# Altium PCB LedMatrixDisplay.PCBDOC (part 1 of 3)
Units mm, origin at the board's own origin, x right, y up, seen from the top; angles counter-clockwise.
Board outline 305.05 x 54.1 mm, 4 copper layers (Top Layer, POWER, GROUND, Bottom Layer); 103 components, 165 nets, 805 pads, 317 vias.
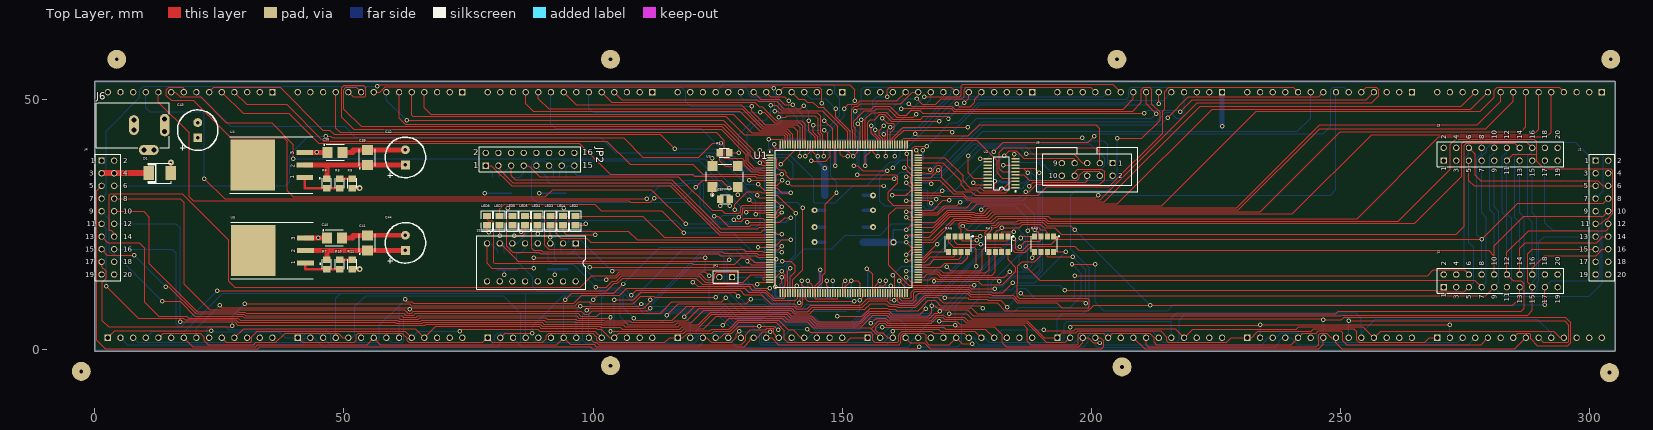
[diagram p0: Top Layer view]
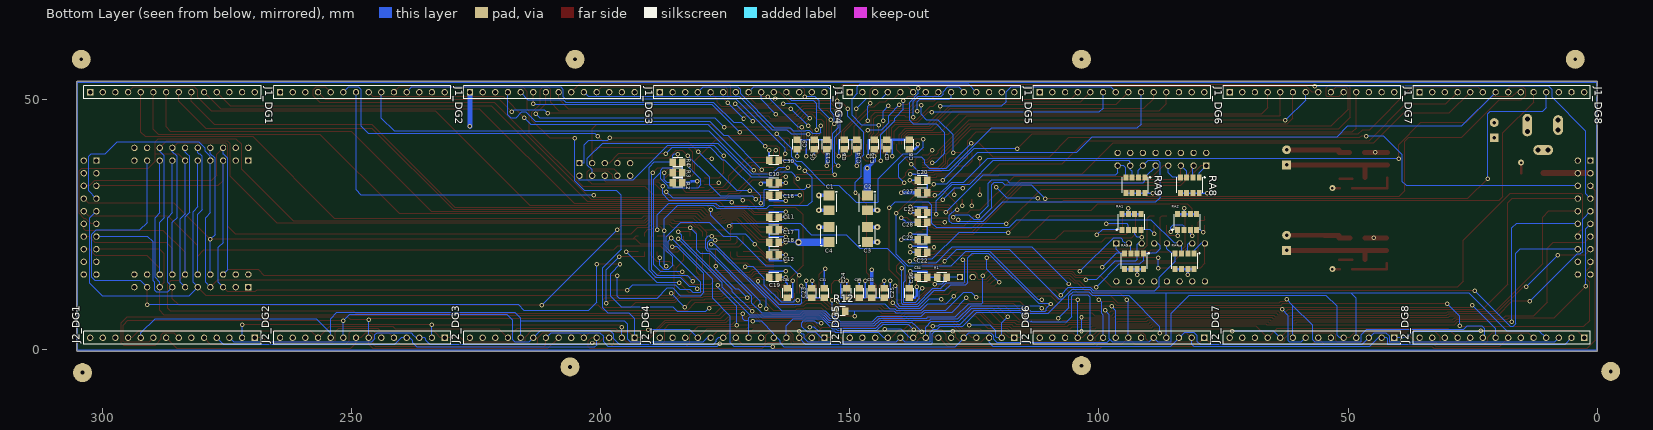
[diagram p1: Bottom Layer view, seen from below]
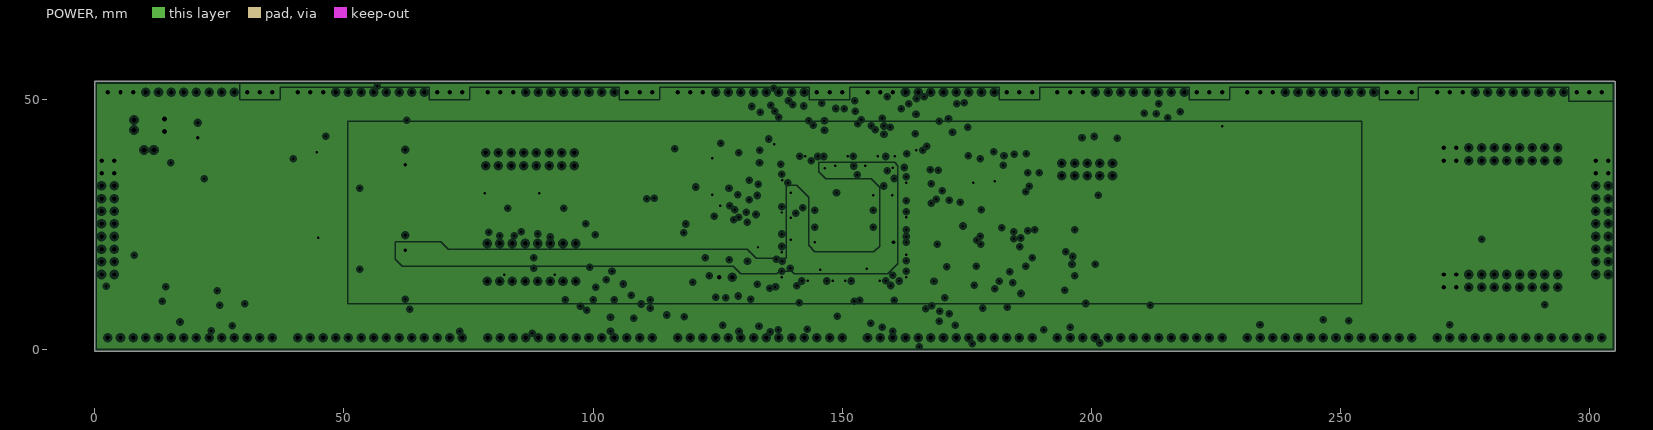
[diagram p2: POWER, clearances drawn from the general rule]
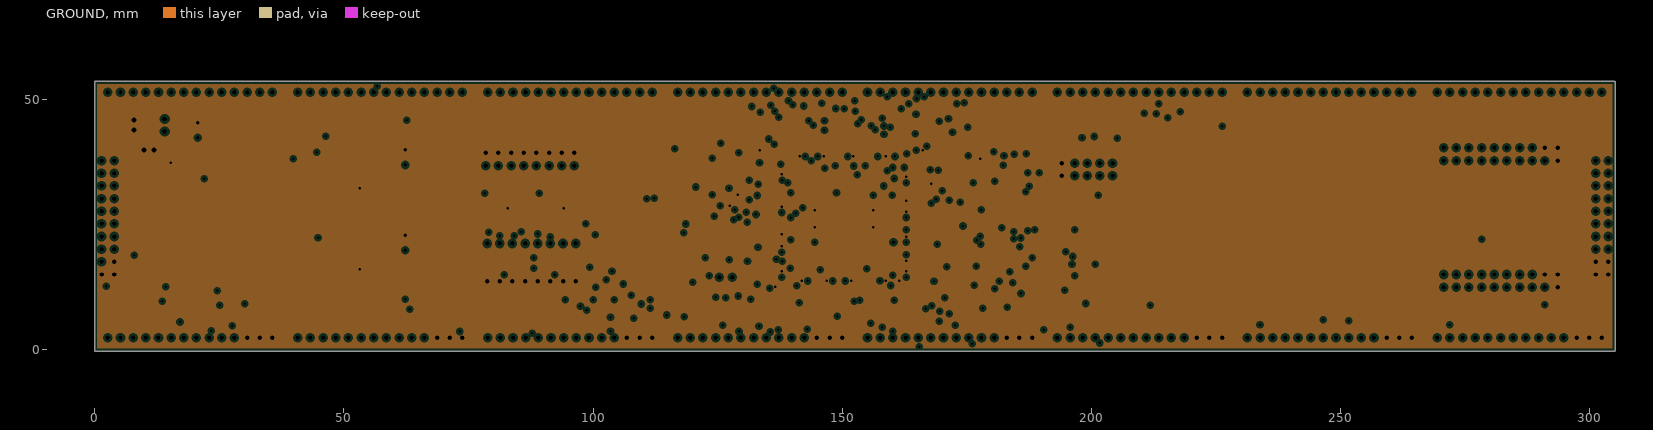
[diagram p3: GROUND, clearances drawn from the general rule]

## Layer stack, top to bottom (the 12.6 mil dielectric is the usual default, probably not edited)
Top Layer: signal copper 0.0356
Dielectric: core 0.32, FR-4, Dk 4.8
POWER: plane copper 0.0356, net (Multiple Nets)
Dielectric: prepreg 0.32, FR-4, Dk 4.8
GROUND: plane copper 0.0356, net GND
Dielectric: core 0.32, FR-4, Dk 4.8
Bottom Layer: signal copper 0.0356

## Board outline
304.927,-0.381 ccw(c304.927,-0.254) 305.055,-0.254 305.055,53.594 ccw(c304.927,53.594) 304.927,53.721 0.127,53.721 ccw(c0.127,53.594) 0,53.594 0,-0.254 ccw(c0.127,-0.254) 0.127,-0.381

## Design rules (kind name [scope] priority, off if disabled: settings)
Clearance [All] p1: gap=0.2
FabricationTestPointUsage TestPointUsage [All] p1: valid=0 allowmultiple=FALSE
FabricationTestpoint Testpoint [All] p1: side=3 testpointundercomponent=TRUE minsize=1.016 maxsize=2.54 preferedsize=1.524 minholesize=0 maxholesize=1.016 preferedholesize=0.813 testpointgrid=0.025 allowsidetop=TRUE allowsidebottom=TRUE usegrid=TRUE gridtolerance=0
HoleSize HoleSize_PowerPads [IsPad And (PadXSize_AllLayers <> PadYSize_AllLayers) And OnMultiLayer] p1: absolutevalues=TRUE maxlimit=2.54 minlimit=0 maxpercent=80.000 minpercent=20.000
HoleSize [All] p2: absolutevalues=TRUE maxlimit=2.54 minlimit=0.025 maxpercent=80.000 minpercent=20.000
PlaneClearance [All] p1: clearance=0.508
PlaneConnect [All] p1: planeconnectstyle=Relief reliefexpansion=0.508 reliefentries=4 reliefconductorwidth=0.254 reliefairgap=0.254
PolygonConnect [All] p1: connectstyle=Relief reliefconductorwidth=0.254 reliefentries=4 polygonreliefangle="90 Angle"
RoomDefinition U_FPGA_U1 [InComponentClass('U_FPGA_U1')] p1: confinementstyle=ConfineIn formatcopy=TRUE lockcomponents=FALSE outline 127.635,6.096 175.895,6.096 175.895,46.736 127.635,46.736
RoomDefinition LED_SW [InComponentClass('LED_SW')] p2: confinementstyle=ConfineIn formatcopy=TRUE lockcomponents=FALSE outline 96.647,13.716 122.047,13.716 122.047,37.846 96.647,37.846
RoomDefinition DG8 [InComponentClass('DG8')] p3: confinementstyle=ConfineIn formatcopy=TRUE lockcomponents=FALSE outline 38.227,-0.254 0.127,-0.254 0.127,53.594 38.227,53.594
RoomDefinition DG7 [InComponentClass('DG7')] p4: confinementstyle=ConfineIn formatcopy=TRUE lockcomponents=FALSE outline 76.327,-0.254 38.227,-0.254 38.227,53.594 76.327,53.594
RoomDefinition DG6 [InComponentClass('DG6')] p5: confinementstyle=ConfineIn formatcopy=TRUE lockcomponents=FALSE outline 114.427,-0.254 76.327,-0.254 76.327,53.594 114.427,53.594
RoomDefinition DG5 [InComponentClass('DG5')] p6: confinementstyle=ConfineIn formatcopy=TRUE lockcomponents=FALSE outline 152.527,-0.254 114.427,-0.254 114.427,53.594 152.527,53.594
RoomDefinition DG3 [InComponentClass('DG3')] p7: confinementstyle=ConfineIn formatcopy=TRUE lockcomponents=FALSE outline 228.727,-0.254 190.627,-0.254 190.627,53.594 228.727,53.594
RoomDefinition DG2 [InComponentClass('DG2')] p8: confinementstyle=ConfineIn formatcopy=TRUE lockcomponents=FALSE outline 266.827,-0.254 228.727,-0.254 228.727,53.594 266.827,53.594
RoomDefinition DG1 [InComponentClass('DG1')] p9: confinementstyle=ConfineIn formatcopy=TRUE lockcomponents=FALSE outline 304.927,-0.254 266.827,-0.254 266.827,53.594 304.927,53.594
RoomDefinition DG4 [InComponentClass('DG4')] p10: confinementstyle=ConfineIn formatcopy=TRUE lockcomponents=FALSE outline 190.627,-0.254 152.527,-0.254 152.527,53.594 190.627,53.594
RoomDefinition PWR [InComponentClass('PWR')] p11: confinementstyle=ConfineIn formatcopy=TRUE lockcomponents=FALSE outline 204.597,13.716 270.637,13.716 270.637,41.656 204.597,41.656
RoutingVias ViasStyle_PowerNets [InNetClass('PowerNets')] p1: holewidth=0.5 width=0.9 viastyle="Through Hole" minholewidth=0.5 minwidth=0.9 maxholewidth=0.5 maxwidth=2.5
RoutingVias [All] p2: holewidth=0.5 width=0.9 viastyle="Through Hole" minholewidth=0.5 minwidth=0.9 maxholewidth=0.5 maxwidth=0.9
SilkscreenOverComponentPads [All] p1: minsilkscreentomaskgap=0.254
SolderMaskExpansion [All] p1: expansion=0.102
Width Width_Power [InNetClass('PowerNets')] p1: maxlimit=2 minlimit=0.2 preferedwidth=0.3 toplayer_prefwidth=0.2 minimp=50.000000 maximp=50.000000 favimp=50.000000
Width [All] p2: maxlimit=2 minlimit=0.2 preferedwidth=0.2
22 further rules are at their usual default settings.

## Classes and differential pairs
net class PowerNets: 6V GND VCCINT VCCO
component class DG1: C45_DG1 C46_DG1 D2_DG1 D3_DG1 GNDTP1_DG1 J1_DG1 J2_DG1 Q1_DG1 Q2_DG1 Q3_DG1 Q4_DG1 Q5_DG1 Q6_DG1 Q7_DG1 Q8_DG1 Q9_DG1 Q10_DG1 Q11_DG1 Q12_DG1 Q13_DG1 Q14_DG1 Q15_DG1 Q16_DG1 R12_DG1 R13_DG1 R14_DG1 R15_DG1 R16_DG1 R17_DG1 R18_DG1 R19_DG1 R20_DG1 R21_DG1 R22_DG1 R23_DG1 R24_DG1 R25_DG1 R26_DG1 TB_DG1 U6_DG1 U7_DG1 U8_DG1 U9_DG1
component class DG2: C45_DG2 C46_DG2 D2_DG2 D3_DG2 GNDTP1_DG2 J1_DG2 J2_DG2 Q1_DG2 Q2_DG2 Q3_DG2 Q4_DG2 Q5_DG2 Q6_DG2 Q7_DG2 Q8_DG2 Q9_DG2 Q10_DG2 Q11_DG2 Q12_DG2 Q13_DG2 Q14_DG2 Q15_DG2 Q16_DG2 R12_DG2 R13_DG2 R14_DG2 R15_DG2 R16_DG2 R17_DG2 R18_DG2 R19_DG2 R20_DG2 R21_DG2 R22_DG2 R23_DG2 R24_DG2 R25_DG2 R26_DG2 TB_DG2 U6_DG2 U7_DG2 U8_DG2 U9_DG2
component class DG3: C45_DG3 C46_DG3 D2_DG3 D3_DG3 GNDTP1_DG3 J1_DG3 J2_DG3 Q1_DG3 Q2_DG3 Q3_DG3 Q4_DG3 Q5_DG3 Q6_DG3 Q7_DG3 Q8_DG3 Q9_DG3 Q10_DG3 Q11_DG3 Q12_DG3 Q13_DG3 Q14_DG3 Q15_DG3 Q16_DG3 R12_DG3 R13_DG3 R14_DG3 R15_DG3 R16_DG3 R17_DG3 R18_DG3 R19_DG3 R20_DG3 R21_DG3 R22_DG3 R23_DG3 R24_DG3 R25_DG3 R26_DG3 TB_DG3 U6_DG3 U7_DG3 U8_DG3 U9_DG3
component class DG4: C45_DG4 C46_DG4 D2_DG4 D3_DG4 GNDTP1_DG4 J1_DG4 J2_DG4 Q1_DG4 Q2_DG4 Q3_DG4 Q4_DG4 Q5_DG4 Q6_DG4 Q7_DG4 Q8_DG4 Q9_DG4 Q10_DG4 Q11_DG4 Q12_DG4 Q13_DG4 Q14_DG4 Q15_DG4 Q16_DG4 R12_DG4 R13_DG4 R14_DG4 R15_DG4 R16_DG4 R17_DG4 R18_DG4 R19_DG4 R20_DG4 R21_DG4 R22_DG4 R23_DG4 R24_DG4 R25_DG4 R26_DG4 TB_DG4 U6_DG4 U7_DG4 U8_DG4 U9_DG4
component class DG5: C45_DG5 C46_DG5 D2_DG5 D3_DG5 GNDTP1_DG5 J1_DG5 J2_DG5 Q1_DG5 Q2_DG5 Q3_DG5 Q4_DG5 Q5_DG5 Q6_DG5 Q7_DG5 Q8_DG5 Q9_DG5 Q10_DG5 Q11_DG5 Q12_DG5 Q13_DG5 Q14_DG5 Q15_DG5 Q16_DG5 R12_DG5 R13_DG5 R14_DG5 R15_DG5 R16_DG5 R17_DG5 R18_DG5 R19_DG5 R20_DG5 R21_DG5 R22_DG5 R23_DG5 R24_DG5 R25_DG5 R26_DG5 TB_DG5 U6_DG5 U7_DG5 U8_DG5 U9_DG5
component class DG6: C45_DG6 C46_DG6 D2_DG6 D3_DG6 GNDTP1_DG6 J1_DG6 J2_DG6 Q1_DG6 Q2_DG6 Q3_DG6 Q4_DG6 Q5_DG6 Q6_DG6 Q7_DG6 Q8_DG6 Q9_DG6 Q10_DG6 Q11_DG6 Q12_DG6 Q13_DG6 Q14_DG6 Q15_DG6 Q16_DG6 R12_DG6 R13_DG6 R14_DG6 R15_DG6 R16_DG6 R17_DG6 R18_DG6 R19_DG6 R20_DG6 R21_DG6 R22_DG6 R23_DG6 R24_DG6 R25_DG6 R26_DG6 TB_DG6 U6_DG6 U7_DG6 U8_DG6 U9_DG6
component class DG7: C45_DG7 C46_DG7 D2_DG7 D3_DG7 GNDTP1_DG7 J1_DG7 J2_DG7 Q1_DG7 Q2_DG7 Q3_DG7 Q4_DG7 Q5_DG7 Q6_DG7 Q7_DG7 Q8_DG7 Q9_DG7 Q10_DG7 Q11_DG7 Q12_DG7 Q13_DG7 Q14_DG7 Q15_DG7 Q16_DG7 R12_DG7 R13_DG7 R14_DG7 R15_DG7 R16_DG7 R17_DG7 R18_DG7 R19_DG7 R20_DG7 R21_DG7 R22_DG7 R23_DG7 R24_DG7 R25_DG7 R26_DG7 TB_DG7 U6_DG7 U7_DG7 U8_DG7 U9_DG7
component class DG8: C45_DG8 C46_DG8 D2_DG8 D3_DG8 GNDTP1_DG8 J1_DG8 J2_DG8 Q1_DG8 Q2_DG8 Q3_DG8 Q4_DG8 Q5_DG8 Q6_DG8 Q7_DG8 Q8_DG8 Q9_DG8 Q10_DG8 Q11_DG8 Q12_DG8 Q13_DG8 Q14_DG8 Q15_DG8 Q16_DG8 R12_DG8 R13_DG8 R14_DG8 R15_DG8 R16_DG8 R17_DG8 R18_DG8 R19_DG8 R20_DG8 R21_DG8 R22_DG8 R23_DG8 R24_DG8 R25_DG8 R26_DG8 TB_DG8 U6_DG8 U7_DG8 U8_DG8 U9_DG8
component class LED_SW: JP2 LED1 LED2 LED3 LED4 LED5 LED6 LED7 LED8 RA1 RA2 RA3 RA4 RA8 RA9 S1
component class LedMatrixDisplay: C37 EN1 J1 J2 J3 J4 J5 R5 R27 RA5 RA6 RA7 U3
component class PWR: C38 C39 C40 C41 C42 C43 C44 D1 J6 R6 R7 R8 R9 R10 R11 U4 U5
component class U_FPGA_U1_Auto: U1
component class U_FPGA_U1: C1 C2 C3 C4 C5 C6 C7 C8 C9 C10 C11 C12 C13 C14 C15 C16 C17 C18 C19 C20 C21 C22 C23 C24 C25 C26 C27 C28 C29 C30 C31 C32 C34 C35 C36 JP1 R1 R2 R3 R4 U2
net class ADDR[2..0]: ADDR0 ADDR1 ADDR2
net class BOARD_ADDR[7..0]: SW0 SW1 SW2 SW3 SW4 SW5 SW6 SW7
net class DATA[7..0]: DATA0 DATA1 DATA2 DATA3 DATA4 DATA5 DATA6 DATA7
net class GREEN[4..0]: GREEN0 GREEN1 GREEN2 GREEN3 GREEN4
net class LED[7..0]: LED0 LED1 LED2 LED3 LED4 LED5 LED6 LED7
net class RED[4..0]: RED0 RED1 RED2 RED3 RED4
net class ROWA[6..0]: ROWA0 ROWA1 ROWA2 ROWA3 ROWA4 ROWA5 ROWA6
net class ROWB[6..0]: ROWB0 ROWB1 ROWB2 ROWB3 ROWB4 ROWB5 ROWB6
net class ROWC[6..0]: ROWC0 ROWC1 ROWC2 ROWC3 ROWC4 ROWC5 ROWC6
net class ROWD[6..0]: ROWD0 ROWD1 ROWD2 ROWD3 ROWD4 ROWD5 ROWD6
net class ROWE[6..0]: ROWE0 ROWE1 ROWE2 ROWE3 ROWE4 ROWE5 ROWE6
net class ROWF[6..0]: ROWF0 ROWF1 ROWF2 ROWF3 ROWF4 ROWF5 ROWF6
net class ROWG[6..0]: ROWG0 ROWG1 ROWG2 ROWG3 ROWG4 ROWG5 ROWG6
net class ROWH[6..0]: ROWH0 ROWH1 ROWH2 ROWH3 ROWH4 ROWH5 ROWH6
net class JUMPERS[7..0]: JUMPERS0 JUMPERS1 JUMPERS2 JUMPERS3 JUMPERS4 JUMPERS5 JUMPERS6 JUMPERS7
channel class DigitHolder: DG1 DG2 DG3 DG4 DG5 DG6 DG7 DG8
net class ENABLE[7..0]: ENABLE0 ENABLE1 ENABLE2 ENABLE3 ENABLE4 ENABLE5 ENABLE6 ENABLE7

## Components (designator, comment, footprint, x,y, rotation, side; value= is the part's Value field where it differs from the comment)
C1 "10uF" MCCT-B 154.177,29.373 r270 bottom locked
C2 "10uF" MCCT-B 146.477,29.373 r270 bottom locked
C3 "10uF" MCCT-B 146.477,22.973 r90 bottom locked
C4 "10uF" MCCT-B 154.177,22.973 r90 bottom locked
C5 "0.1uF" CC2012-0805 157.077,41.073 r270 bottom
C6 "0.1uF" CC2012-0805 151.077,41.073 r270 bottom
C7 "0.1uF" CC2012-0805 142.577,41.073 r270 bottom
C8 "0.1uF" CC2012-0805 138.077,41.073 r270 bottom
C9 "0.1uF" CC2012-0805 160.577,41.073 r270 bottom
C10 "0.1uF" CC2012-0805 165.227,33.423 r180 bottom
C11 "0.1uF" CC2012-0805 165.227,26.423 r180 bottom
C12 "0.1uF" CC2012-0805 165.227,18.923 r180 bottom
C13 "0.1uF" CC2012-0805 154.577,41.073 r270 bottom
C14 "0.1uF" CC2012-0805 148.577,41.073 r270 bottom
C15 "0.1uF" CC2012-0805 145.077,41.073 r270 bottom
C16 "0.1uF" CC2012-0805 165.227,30.923 r180 bottom
C17 "0.1uF" CC2012-0805 165.227,23.923 r180 bottom
C18 "0.1uF" CC2012-0805 165.227,21.423 r180 bottom
C19 "0.1uF" CC2012-0805 165.227,14.423 r0 bottom
C20 "0.1uF" CC2012-0805 135.427,33.923 r180 bottom
C21 "0.1uF" CC2012-0805 135.427,27.423 r180 bottom
C22 "0.1uF" CC2012-0805 135.427,19.423 r180 bottom
C23 "0.1uF" CC2012-0805 157.577,11.273 r270 bottom
C24 "0.1uF" CC2012-0805 150.577,11.273 r270 bottom
C25 "0.1uF" CC2012-0805 143.077,11.273 r270 bottom
C26 "0.1uF" CC2012-0805 138.077,11.273 r270 bottom
C27 "0.1uF" CC2012-0805 135.427,31.423 r180 bottom
C28 "0.1uF" CC2012-0805 135.427,25.423 r180 bottom
C29 "0.1uF" CC2012-0805 135.427,21.923 r180 bottom
C30 "0.1uF" CC2012-0805 165.227,37.923 r0 bottom
C31 "0.1uF" CC2012-0805 155.077,11.273 r270 bottom
C32 "0.1uF" CC2012-0805 145.577,11.273 r270 bottom
C34 "100nF" CC2012-0805 135.427,14.423 r0 bottom
C35 "100nF" CC2012-0805 148.077,11.273 r90 bottom
C36 "100nF" CC2012-0805 162.577,11.273 r90 bottom
C37 "100nF" CC2012-0805 126.492,30.099 r0 top
C38 "10uF" MCCT-B 48.26,39.497 r0 top locked
C39 "10uF" MCCT-B 54.737,38.457 r90 top locked
C40 "10uF" MCCT-B 48.109,22.352 r0 top locked
C41 "10uF" MCCT-B 54.737,21.312 r90 top locked
C42 "470uF 16V" RB8/3.5 62.357,38.481 r180 top
C43 "470uF 16V" RB8/3.5 20.701,43.942 r180 top
C44 "470uF 16V" RB8/3.5 62.357,21.336 r180 top
D1 "SMBJ5341B" DO214 13.081,35.306 r180 top
J1 "Header 20" HDR2X10 301.117,37.846 r270 top
J1_DG1 "Header 14" HDR1X14 302.387,51.562 r180 bottom (schematic designator J1)
J1_DG2 "Header 14" HDR1X14 264.287,51.562 r180 bottom (schematic designator J1)
J1_DG3 "Header 14" HDR1X14 226.187,51.562 r180 bottom (schematic designator J1)
J1_DG4 "Header 14" HDR1X14 188.087,51.562 r180 bottom (schematic designator J1)
J1_DG5 "Header 14" HDR1X14 149.987,51.562 r180 bottom (schematic designator J1)
J1_DG6 "Header 14" HDR1X14 111.887,51.562 r180 bottom (schematic designator J1)
J1_DG7 "Header 14" HDR1X14 73.787,51.562 r180 bottom (schematic designator J1)
J1_DG8 "Header 14" HDR1X14 35.687,51.562 r180 bottom (schematic designator J1)
J2 "Header 20" HDR2X10 270.637,12.446 r0 top
J2_DG1 "Header 14" HDR1X14 269.367,2.286 r0 bottom (schematic designator J2)
J2_DG2 "Header 14" HDR1X14 231.267,2.286 r0 bottom (schematic designator J2)
J2_DG3 "Header 14" HDR1X14 193.167,2.286 r0 bottom (schematic designator J2)
J2_DG4 "Header 14" HDR1X14 155.067,2.286 r0 bottom (schematic designator J2)
J2_DG5 "Header 14" HDR1X14 116.967,2.286 r0 bottom (schematic designator J2)
J2_DG6 "Header 14" HDR1X14 78.867,2.286 r0 bottom (schematic designator J2)
J2_DG7 "Header 14" HDR1X14 40.767,2.286 r0 bottom (schematic designator J2)
J2_DG8 "Header 14" HDR1X14 2.667,2.286 r0 bottom (schematic designator J2)
J3 "Header 20" HDR2X10 270.637,37.846 r0 top
J4 "Header 20" HDR2X10 1.397,37.846 r270 top
J5 "70246-1022" HDR2X5_LP 204.217,37.338 r180 top
J6 "KLD-0202-B" KLD-0202 0.381,44.958 r0 top
JP1 "Header 2" HDR1X2 127.889,14.478 r180 top
JP2 "Header 8X2" HDR2X8 78.487,36.83 r0 top
LED1 "HSMH-C170" "SMD _LED" 93.98,25.781 r90 top
LED2 "HSMH-C170" "SMD _LED" 96.52,25.781 r90 top
LED3 "HSMH-C170" "SMD _LED" 91.44,25.781 r90 top
LED4 "HSMH-C170" "SMD _LED" 88.9,25.781 r90 top
LED5 "HSMH-C170" "SMD _LED" 86.36,25.781 r90 top
LED6 "HSMH-C170" "SMD _LED" 83.82,25.781 r90 top
LED7 "HSMH-C170" "SMD _LED" 81.28,25.781 r90 top
LED8 "HSMH-C170" "SMD _LED" 78.74,25.781 r90 top
R1 "1K" CC2012-0805 131.495,14.423 r180 bottom
R2 "4K7" CC2012-0805 184.531,33.401 r0 bottom
R3 "4K7" CC2012-0805 184.531,35.433 r0 bottom
R4 "4K7" CC2012-0805 184.531,37.465 r0 bottom
R5 "33R" CC2012-0805 126.365,39.37 r0 top
R6 "120R" CC2012-0805 46.609,33.274 r270 top locked
R7 "120R" CC2012-0805 46.609,17.018 r270 top locked
R8 "100R" CC2012-0805 49.149,33.274 r90 top locked
R9 "100R" CC2012-0805 51.689,33.274 r90 top locked
R10 "47R" CC2012-0805 49.149,17.018 r90 top locked
R11 "5R6" CC2012-0805 51.689,17.018 r270 top locked
R12 "47R" CC2012-0805 151.892,7.62 r180 bottom
RA1 "270R" MNR34 93.472,25.527 r90 bottom
RA2 "270R" MNR34 82.296,25.527 r90 bottom
RA3 "4K7" MNR34 92.964,17.653 r270 bottom
RA4 "4K7" MNR34 82.804,17.653 r270 bottom
RA5 "47R" MNR34 190.501,21.082 r270 top
RA6 "47R" MNR34 173.229,21.082 r270 top
RA7 "47R" MNR34 181.357,21.082 r270 top
RA8 "4K7" MNR34 81.788,32.893 r270 bottom
RA9 "4K7" MNR34 92.71,32.893 r270 bottom
S1 "A6ER-8104" DIP-16-KEY 96.52,21.209 r180 top
U1 "XC2S300E-6PQ208C" PQ208 150.327,26.173 r0 top locked
U2 "XCF02SVO20C" VO20 181.991,35.306 r90 top
U3 "QSMO_4200" QSMO_4200 123.952,32.131 r0 top
U4 "LM1084IS-ADJ" TO-263 42.164,34.417 r90 top
U5 "LM1084IS-ADJ" TO-263 42.291,17.272 r90 top

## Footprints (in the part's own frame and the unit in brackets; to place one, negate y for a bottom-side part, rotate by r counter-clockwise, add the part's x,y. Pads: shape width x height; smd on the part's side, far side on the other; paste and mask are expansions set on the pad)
CC2012-0805 [mm]
  rect 1.3x1.5 smd: 1(-0.95,0) 2(0.95,0)
  silkscreen extent -1,-0.9 1,0.9
DIP-16-KEY [mm]
  rect 1.27x1.27 hole 0.9: 1(0,0)
  round 1.27 hole 0.9: 2(2.54,0) 3(5.08,0) 4(7.62,0) 5(10.16,0) 6(12.7,0) 7(15.24,0) 8(17.78,0) 9(17.78,7.62) 10(15.24,7.62) 11(12.7,7.62) 12(10.16,7.62) 13(7.62,7.62) 14(5.08,7.62) 15(2.54,7.62) 16(0,7.62)
  silkscreen extent -2.05,-1.59 19.83,9.2
DO214 [mil]
  rect 85x110 smd: 1(-87.5,0) 2(87.5,0)
  silkscreen extent -90,-78 90,78
HDR1X2 [mm]
  rect 1.27x1.27 hole 0.9: 1(0,0)
  round 1.27 hole 0.9: 2(2.54,0)
  silkscreen extent -1.27,-1.27 3.81,1.27
HDR1X14 [mm]
  rect 1.27x1.27 hole 0.9: 1(0,0)
  round 1.27 hole 0.9: 2(2.54,0) 3(5.08,0) 4(7.62,0) 5(10.16,0) 6(12.7,0) 7(15.24,0) 8(17.78,0) 9(20.32,0) 10(22.86,0) 11(25.4,0) 12(27.94,0) 13(30.48,0) 14(33.02,0)
  silkscreen extent -1.27,-1.27 34.29,1.27
HDR2X5_LP [mm]
  rect 1.27x1.27 hole 0.9: 1(0,0)
  round 1.27 hole 0.9: 2(0,2.54) 3(2.54,0) 4(2.54,2.54) 5(5.08,0) 6(5.08,2.54) 7(7.62,0) 8(7.62,2.54) 9(10.16,0) 10(10.16,2.54)
  silkscreen extent -5.08,-3.18 15.24,5.72
HDR2X8 [mm]
  rect 1.27x1.27 hole 0.9: 1(0,0)
  round 1.27 hole 0.9: 2(0,2.54) 3(2.54,0) 4(2.54,2.54) 5(5.08,0) 6(5.08,2.54) 7(7.62,0) 8(7.62,2.54) 9(10.16,0) 10(10.16,2.54) 11(12.7,0) 12(12.7,2.54) 13(15.24,0) 14(15.24,2.54) 15(17.78,0) 16(17.78,2.54)
  silkscreen extent -1.27,-1.27 19.05,3.81
HDR2X10 [mm]
  rect 1.27x1.27 hole 0.9: 1(0,0)
  round 1.27 hole 0.9: 2(0,2.54) 3(2.54,0) 4(2.54,2.54) 5(5.08,0) 6(5.08,2.54) 7(7.62,0) 8(7.62,2.54) 9(10.16,0) 10(10.16,2.54) 11(12.7,0) 12(12.7,2.54) 13(15.24,0) 14(15.24,2.54) 15(17.78,0) 16(17.78,2.54) 17(20.32,0) 18(20.32,2.54) 19(22.86,0) 20(22.86,2.54)
  silkscreen extent -1.27,-1.27 24.13,3.81
KLD-0202 [mm] "PCB Mount DC Power Jack with 2.1mm or 2.5mm center pin"
  oval 2x4.5 all layers, no hole: 1(13.7,0)
  round 1.5 hole 1: 1A(13.7,-1.25) 1B(13.7,1.25) 2A(9.5,-5) 2B(11.5,-5) 3A(7.5,-1) 3B(7.5,1)
  oval 4x2 all layers, no hole: 2(10.5,-5)
  oval 2x4 all layers, no hole: 3(7.5,0)
  silkscreen extent 0,-4.5 14.6,4.5
MCCT-B [mm]
  rect 2x2.2 smd: 1(-1.5,0) 2(1.5,0)
  silkscreen extent -2.3,-1.6 1.8,1.6
MNR34 [mm]
  rect 1.2x1 smd: 1(-1.575,1.905) 2(-1.575,0.635) 3(-1.575,-0.635) 4(-1.575,-1.905) 5(1.575,-1.905) 6(1.575,-0.635) 7(1.575,0.635) 8(1.575,1.905)
  silkscreen extent -1.67,-2.62 1.55,3.07
PQ208 [mm] "208-Pin Plastic Quad Flat Pack (PQ208)"
  rect 1.55x0.3 smd: 1(-14.9,12.75) 2(-14.9,12.25) 3(-14.9,11.75) 4(-14.9,11.25) 5(-14.9,10.75) 6(-14.9,10.25) 7(-14.9,9.75) 8(-14.9,9.25) 9(-14.9,8.75) 10(-14.9,8.25) 11(-14.9,7.75) 12(-14.9,7.25) 13(-14.9,6.75) 14(-14.9,6.25) 15(-14.9,5.75) 16(-14.9,5.25) 17(-14.9,4.75) 18(-14.9,4.25) 19(-14.9,3.75) 20(-14.9,3.25) 21(-14.9,2.75) 22(-14.9,2.25) 23(-14.9,1.75) 24(-14.9,1.25) 25(-14.9,0.75) 26(-14.9,0.25) 27(-14.9,-0.25) 28(-14.9,-0.75) 29(-14.9,-1.25) 30(-14.9,-1.75) 31(-14.9,-2.25) 32(-14.9,-2.75) 33(-14.9,-3.25) 34(-14.9,-3.75) 35(-14.9,-4.25) 36(-14.9,-4.75) 37(-14.9,-5.25) 38(-14.9,-5.75) 39(-14.9,-6.25) 40(-14.9,-6.75) 41(-14.9,-7.25) 42(-14.9,-7.75) 43(-14.9,-8.25) 44(-14.9,-8.75) 45(-14.9,-9.25) 46(-14.9,-9.75) 47(-14.9,-10.25) 48(-14.9,-10.75) 49(-14.9,-11.25) 50(-14.9,-11.75) 51(-14.9,-12.25) 52(-14.9,-12.75) 105(14.9,-12.75) 106(14.9,-12.25) 107(14.9,-11.75) 108(14.9,-11.25) 109(14.9,-10.75) 110(14.9,-10.25) 111(14.9,-9.75) 112(14.9,-9.25) 113(14.9,-8.75) 114(14.9,-8.25) 115(14.9,-7.75) 116(14.9,-7.25) 117(14.9,-6.75) 118(14.9,-6.25) 119(14.9,-5.75) 120(14.9,-5.25) 121(14.9,-4.75) 122(14.9,-4.25) 123(14.9,-3.75) 124(14.9,-3.25) 125(14.9,-2.75) 126(14.9,-2.25) 127(14.9,-1.75) 128(14.9,-1.25) 129(14.9,-0.75) 130(14.9,-0.25) 131(14.9,0.25) 132(14.9,0.75) 133(14.9,1.25) 134(14.9,1.75) 135(14.9,2.25) 136(14.9,2.75) 137(14.9,3.25) 138(14.9,3.75) 139(14.9,4.25) 140(14.9,4.75) 141(14.9,5.25) 142(14.9,5.75) 143(14.9,6.25) 144(14.9,6.75) 145(14.9,7.25) 146(14.9,7.75) 147(14.9,8.25) 148(14.9,8.75) 149(14.9,9.25) 150(14.9,9.75) 151(14.9,10.25) 152(14.9,10.75) 153(14.9,11.25) 154(14.9,11.75) 155(14.9,12.25) 156(14.9,12.75)
  rect 0.3x1.55 smd: 53(-12.75,-14.9) 54(-12.25,-14.9) 55(-11.75,-14.9) 56(-11.25,-14.9) 57(-10.75,-14.9) 58(-10.25,-14.9) 59(-9.75,-14.9) 60(-9.25,-14.9) 61(-8.75,-14.9) 62(-8.25,-14.9) 63(-7.75,-14.9) 64(-7.25,-14.9) 65(-6.75,-14.9) 66(-6.25,-14.9) 67(-5.75,-14.9) 68(-5.25,-14.9) 69(-4.75,-14.9) 70(-4.25,-14.9) 71(-3.75,-14.9) 72(-3.25,-14.9) 73(-2.75,-14.9) 74(-2.25,-14.9) 75(-1.75,-14.9) 76(-1.25,-14.9) 77(-0.75,-14.9) 78(-0.25,-14.9) 79(0.25,-14.9) 80(0.75,-14.9) 81(1.25,-14.9) 82(1.75,-14.9) 83(2.25,-14.9) 84(2.75,-14.9) 85(3.25,-14.9) 86(3.75,-14.9) 87(4.25,-14.9) 88(4.75,-14.9) 89(5.25,-14.9) 90(5.75,-14.9) 91(6.25,-14.9) 92(6.75,-14.9) 93(7.25,-14.9) 94(7.75,-14.9) 95(8.25,-14.9) 96(8.75,-14.9) 97(9.25,-14.9) 98(9.75,-14.9) 99(10.25,-14.9) 100(10.75,-14.9) 101(11.25,-14.9) 102(11.75,-14.9) 103(12.25,-14.9) 104(12.75,-14.9) 157(12.75,14.9) 158(12.25,14.9) 159(11.75,14.9) 160(11.25,14.9) 161(10.75,14.9) 162(10.25,14.9) 163(9.75,14.9) 164(9.25,14.9) 165(8.75,14.9) 166(8.25,14.9) 167(7.75,14.9) 168(7.25,14.9) 169(6.75,14.9) 170(6.25,14.9) 171(5.75,14.9) 172(5.25,14.9) 173(4.75,14.9) 174(4.25,14.9) 175(3.75,14.9) 176(3.25,14.9) 177(2.75,14.9) 178(2.25,14.9) 179(1.75,14.9) 180(1.25,14.9) 181(0.75,14.9) 182(0.25,14.9) 183(-0.25,14.9) 184(-0.75,14.9) 185(-1.25,14.9) 186(-1.75,14.9) 187(-2.25,14.9) 188(-2.75,14.9) 189(-3.25,14.9) 190(-3.75,14.9) 191(-4.25,14.9) 192(-4.75,14.9) 193(-5.25,14.9) 194(-5.75,14.9) 195(-6.25,14.9) 196(-6.75,14.9) 197(-7.25,14.9) 198(-7.75,14.9) 199(-8.25,14.9) 200(-8.75,14.9) 201(-9.25,14.9) 202(-9.75,14.9) 203(-10.25,14.9) 204(-10.75,14.9) 205(-11.25,14.9) 206(-11.75,14.9) 207(-12.25,14.9) 208(-12.75,14.9)
  silkscreen extent -15.02,-13.73 13.72,13.73
QSMO_4200 [mm]
  rect 2x2 smd: 1(0,0.4) 2(5.08,0.4) 3(5.08,4.6) 4(0,4.6)
  silkscreen extent -1.19,-1.31 6.22,4.95
RB8/3.5 [mil]
  rect 70x70 hole 27.56: 1(0,60)
  round 70 hole 27.56: 2(0,-60)
  silkscreen extent -160,-160 160,160
"SMD _LED" [mm]
  rect 1.3x1.6 smd: 1(0.94,0) 2(-0.96,0)
  silkscreen extent -2.14,-1.15 1.99,1.15
TO-263 [mm]
  rect 1x3.4 smd: 1(0,0) 2(2.54,0) 3(5.08,0)
  rect 10.25x8.9 smd: 4(2.54,10.45)
  silkscreen extent -3.1,-3.13 8.2,15
VO20 [mm]
  rect 0.3x1.65 smd: 1(-2.929,-2.766) 2(-2.279,-2.766) 3(-1.629,-2.766) 4(-0.979,-2.766) 5(-0.329,-2.766) 6(0.321,-2.766) 7(0.971,-2.766) 8(1.621,-2.766) 9(2.271,-2.766) 10(2.921,-2.766) 11(2.921,2.784) 12(2.271,2.784) 13(1.621,2.784) 14(0.971,2.784) 15(0.321,2.784) 16(-0.329,2.784) 17(-0.979,2.784) 18(-1.629,2.784) 19(-2.279,2.784) 20(-2.929,2.784)
  silkscreen extent -3.75,-2.89 3.3,1.56

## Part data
C1 C2 C3 C4 C38 C39 C40 C41 C42 C43 C44: library part CAP_POLAR, "Polar Capacitor"
C5 C6 C7 C8 C9 C10 C11 C12 C13 C14 C15 C16 C17 C18 C19 C20 C21 C22 C23 C24 C25 C26 C27 C28 C29 C30 C31 C32 C34 C35 C36 C37: library part CAP, "Capacitor"
D1: library part BZG03C13, "Zener Diode, 6.2V, 5W"
J1 J2 J3 J4: "Header, 20-Pin"
J1_DG1 J1_DG2 J1_DG3 J1_DG4 J1_DG5 J1_DG6 J1_DG7 J1_DG8 J2_DG1 J2_DG2 J2_DG3 J2_DG4 J2_DG5 J2_DG6 J2_DG7 J2_DG8: "Header, 14-Pin"
J5: library part "Header 5X2", "Header, 5-Pin, Dual row"
J6: "Low Voltage Power Supply Connector"
JP1: "Header, 2-Pin"
JP2: "Header, 8-Pin, Dual row"
LED1 LED2 LED3 LED4 LED5 LED6 LED7 LED8: library part HSMX-C670, "Typical RED GaAs SMD LED Agilent make"
R1 R2 R3 R4 R5 R6 R7 R8 R9 R10 R11 R12: library part RES, "Resistor"
RA1 RA2 RA3 RA4 RA5 RA6 RA7 RA8 RA9: library part MNR34, "3216x4 Resistor Array"
S1: "DIP Switch Side actuator long liver Piano Key"
U1: "Spartan-IIE 1.8V FPGA, 208-Pin PQFP, Standard Performance, Commercial Grade"
U2: "XCF00S Series, Platform Flash In-System Programmable Configuration 3.3V PROM, 20-Pin TSOP, 2-Megabit, Commercial Grade"
U3: "Surface Mount Crystal Oscillator"
U4 U5: "5A Low Dropout Possitive Regulators"

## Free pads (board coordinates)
  round 3.81 hole 0.762: 1(4.445,58.166) 2(304.165,58.166) 3(303.911,-4.699) 4(-2.667,-4.445) 5(103.505,58.166) 6(205.105,58.166) 7(103.505,-3.302) 8(206.121,-3.556)

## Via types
v1: diameter 0.9, hole 0.5, Top Layer to Bottom Layer, 307 vias
v2: diameter 1.2, hole 0.5, Top Layer to Bottom Layer, 9 vias
v3: diameter 1.27, hole 0.711, Top Layer to Bottom Layer, 1 vias

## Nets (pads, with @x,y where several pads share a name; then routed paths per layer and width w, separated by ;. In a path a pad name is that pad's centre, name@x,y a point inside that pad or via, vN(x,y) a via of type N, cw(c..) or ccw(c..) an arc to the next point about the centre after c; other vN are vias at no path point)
6V: C38.1 C40.1 C43.1 D1.2 J1.1 J1.2 J1.3 J1.4 J1_DG1.12 J1_DG1.13 J1_DG1.14 J1_DG2.12 J1_DG2.13 J1_DG2.14 J1_DG3.12 J1_DG3.13 J1_DG3.14 J1_DG4.12 J1_DG4.13 J1_DG4.14 J1_DG5.12 J1_DG5.13 J1_DG5.14 J1_DG6.12 J1_DG6.13 J1_DG6.14 J1_DG7.12 J1_DG7.13 J1_DG7.14 J1_DG8.12 J1_DG8.13 J1_DG8.14 J2.1 J2.2 J2.3 J2.4 J3.1 J3.2 J3.3 J3.4 J4.1 J4.2 J4.3 J4.4 J6.1 J6.1A J6.1B U4.3 U5.3 | length 18.4
  Top Layer w1: U4.3@42.164,39.497 v1(44.577,39.497) C38.1@46.76,39.497 ; U5.3@42.291,22.352 v1(44.831,22.352) C40.1@46.609,22.352
  Top Layer w1.2: J4.3@1.397,35.306 J4.4@3.937,35.306 D1.2@10.859,35.306
ADDR0: RA7.5 U1.110 | length 18.3
  Top Layer w0.2: U1.110@165.227,15.923 169.599,15.923 170.231,15.291 178.791,15.291 179.452,15.952 RA7.5@179.452,19.507
ADDR1: RA7.6 U1.109 | length 20
  Top Layer w0.2: U1.109@165.227,15.423 166.193,15.423 166.263,15.494 169.215,15.494 169.825,14.884 180.061,14.884 180.722,15.545 RA7.6@180.722,19.507
ADDR2: RA7.7 U1.97 | length 33.3
  Top Layer w0.2: U1.97@159.577,11.273 159.577,9.779 v1(160.401,9.779) ; v1(170.942,16.51) 171.755,15.697 177.673,15.697 178.08,16.104 178.08,19.812 178.689,20.422 181.738,20.422 181.992,20.168 RA7.7@181.992,19.507
  Bottom Layer w0.2: v1(160.401,9.779) 161.163,9.779 161.163,9.373 163.653,9.373 167.132,12.852 167.132,14.275 169.368,16.51 v1(170.942,16.51)
CCLK: U1.155 U2.3 | length 23.6
  Top Layer w0.2: U1.155@165.227,38.423 170.568,38.423 174.244,34.747 174.244,33.782 175.591,32.436 177.724,32.436 178.334,31.826 181.915,31.826 183.766,33.677 U2.3@184.758,33.677
CLK_MHZ40: R5.2 U1.185 | length 34.3
  Top Layer w0.2: R5.2@127.315,39.37 v1(129.21,39.37) ; v1(135.662,48.946) 136.779,48.946 137.897,47.828 145.974,47.828 149.077,44.725 U1.185@149.077,41.073
  Bottom Layer w0.2: v1(129.21,39.37) 129.21,42.977 132.207,45.974 134.519,45.974 135.662,47.117 v1(135.662,48.946)
CNT5: J1.5 J2.5 J3.5 J4.5 RA5.4 | length 403.1
  Top Layer w0.2: J4.5@1.397,32.766 0.458,31.826 0.458,1.778 2.109,0.127 32.766,0.127 33.173,0.533 99.467,0.533 99.873,0.127 164.999,0.127 v1(165.405,0.533) ; v1(185.801,22.25) 186.208,22.657 ; v1(185.801,22.377) 186.081,22.657 RA5.4@188.596,22.657 ; v1(194.615,11.811) 268.986,11.811 269.317,11.481 274.752,11.481 J2.5@275.717,12.446 ; J3.5@275.717,37.846 275.717,33.782 276.733,32.766 J1.5@301.117,32.766
  Bottom Layer w0.2: v1(165.405,0.533) 173.203,0.533 173.94,1.27 173.94,6.655 177.47,10.185 177.47,14.046 v1(185.801,22.377) ; v1(185.801,22.25) 186.36,21.692 186.36,19.964 179.858,13.462 179.858,11.582 180.112,11.328 181.407,11.328 182.017,11.938 183.965,11.938 184.854,12.827 193.599,12.827 v1(194.615,11.811) ; J2.5@275.717,12.446 276.657,13.386 276.657,20.447 275.717,21.387 J3.5@275.717,37.846
CNT6: J1.6 J2.6 J3.6 J4.6 RA5.3 | length 395.8
  Top Layer w0.2: v1(46.381,42.748) 47.422,42.748 47.752,42.418 106.122,42.418 110.008,38.532 121.235,38.532 124.054,41.351 v1(125.603,41.351) ; v1(139.065,33.401) 139.725,32.741 v1(158.319,32.741) ; v1(185.598,20.574) 186.716,21.692 189.662,21.692 189.866,21.895 RA5.3@189.866,22.657 189.408,22.657 189.408,23.571 188.951,23.571 v1(188.595,23.927) ; v1(196.596,14.732) 196.647,14.783 267.437,14.783 268.58,15.926 274.778,15.926 J2.6@275.717,14.986 ; J3.6@275.717,40.386 276.987,39.116 276.987,34.874 278.054,33.807 301.549,33.807 302.591,32.766 J1.6@303.657,32.766
  Bottom Layer w0.2: J4.6@3.937,32.766 38.278,32.766 39.142,33.63 39.142,38.989 42.901,42.748 v1(46.381,42.748) ; v1(125.603,41.351) 130.734,36.22 133.985,36.22 134.576,36.811 134.972,37.208 134.972,37.944 135.509,38.481 138.811,38.481 140.208,37.084 140.208,34.544 v1(139.065,33.401) ; v1(158.319,32.741) 159.081,31.979 167.132,31.979 167.132,28.905 167.488,28.55 176.099,28.55 176.734,29.185 186.411,29.185 188.595,27 v1(188.595,23.927) ; v1(185.598,20.574) 184.564,20.574 179.248,15.258 179.248,11.43 180.01,10.668 183.896,10.668 185.42,12.192 186.69,12.192 188.722,10.16 196.088,10.16 196.596,10.668 v1(196.596,14.732) ; J2.6@275.717,14.986 274.778,15.926 274.778,38.278 275.616,39.116 275.717,39.116 J3.6@275.717,40.386
CNT7: J1.7 J2.7 J3.7 J4.7 RA5.2 | length 402.8
  Top Layer w0.2: v1(56.693,52.781) 56.998,53.086 151.461,53.086 152.477,52.07 v1(152.477,49.86) ; v1(152.324,36.754) 153.137,36.754 154.077,35.814 v1(159.004,35.814) ; v1(186.767,16.662) 189.637,13.792 276.911,13.792 J2.7@278.257,12.446 ; v1(187.173,23.724) 188.126,24.677 189.11,24.677 189.834,23.952 190.577,23.952 191.136,23.393 RA5.2@191.136,22.657
  Bottom Layer w0.2: J4.7@1.397,30.226 2.337,31.166 2.337,43.764 9.094,50.521 9.094,52.07 9.805,52.781 v1(56.693,52.781) ; v1(152.324,36.754) 152.959,37.389 152.959,42.52 151.867,43.612 151.867,49.251 v1(152.477,49.86) ; v1(159.004,35.814) 157.557,34.367 157.557,29.718 158.522,28.753 166.116,28.753 166.726,28.143 176.607,28.143 177.242,28.778 184.608,28.778 187.173,26.213 187.173,17.069 v1(186.767,16.662) ; J2.7@278.257,12.446 279.197,13.386 279.197,26.416 278.257,27.356 J3.7@278.257,37.846 278.257,38.659 279.299,39.7 279.299,40.361 280.493,41.554 297.028,41.554 299.466,39.116 302.26,39.116 302.641,38.735 302.641,31.75 J1.7@301.117,30.226
CNT8: J1.8 J2.8 J3.8 J4.8 RA5.1 | length 363.2
  Top Layer w0.2: J4.8@3.937,30.226 17.145,30.226 17.958,29.413 17.958,13.056 23.114,7.899 62.18,7.899 62.853,7.226 63.614,7.226 63.958,7.569 97.675,7.569 98.222,7.022 99.149,7.022 99.848,7.722 110.973,7.722 v1(111.506,8.255) ; v1(184.43,22.149) 184.811,21.768 184.811,20.168 185.166,19.812 186.208,19.812 187.427,21.031 191.948,21.031 192.939,22.022 v1(278.257,22.022) 285.496,29.261 302.692,29.261 J1.8@303.657,30.226 ; RA5.1@192.406,22.657 192.939,22.657 193.574,22.022
  Bottom Layer w0.2: v1(111.506,8.255) 111.913,8.661 125.73,8.661 128.422,5.969 133.858,5.969 134.074,5.753 144.018,5.753 145.199,4.572 152.158,4.572 153.339,5.753 154.075,5.753 155.129,6.807 169.952,6.807 175.565,12.421 175.565,13.284 v1(184.43,22.149) ; J2.8@278.257,14.986 v1(278.257,22.022) 277.318,22.962 277.318,38.303 278.257,39.243 J3.8@278.257,40.386
CNT9: J1.9 J2.9 J3.9 J4.9 RA6.4 | length 384
  Top Layer w0.2: v1(13.615,9.601) 17.171,9.601 20.114,6.658 29.617,6.658 30.001,6.274 61.042,6.274 61.296,6.02 64.948,6.02 65.202,6.274 90.551,6.274 90.856,5.969 96.628,5.969 96.774,5.822 102.179,5.822 102.312,5.69 107.392,5.69 107.722,5.359 116.129,5.359 116.459,5.69 118.771,5.69 121.285,8.204 139.827,8.204 140.513,7.518 143.079,7.518 143.942,8.382 154.051,8.382 155.375,9.706 158.95,9.706 159.639,9.017 161.182,9.017 161.367,8.832 164.534,8.832 166.554,10.852 169.996,10.852 v1(170.561,10.287) 175.133,10.287 175.387,10.033 179.07,10.033 179.324,9.779 181.814,9.779 v1(183.134,8.458) ; RA6.4@171.324,22.657 171.324,21.488 172.391,20.422 176.454,20.422 176.911,19.964 v1(176.911,16.612) ; v1(185.852,11.176) 186.259,10.77 279.121,10.77 J2.9@280.797,12.446
  Bottom Layer w0.2: J4.9@1.397,27.686 2.998,26.086 2.998,19.558 3.506,19.05 4.166,19.05 v1(13.615,9.601) ; v1(170.561,10.287) 172.258,11.984 172.843,11.984 176.911,16.053 v1(176.911,16.612) ; v1(183.134,8.458) v1(185.852,11.176) ; J3.9@280.797,37.846 280.797,28.55 281.737,27.61 281.737,13.386 J2.9@280.797,12.446 282.626,10.617 299.873,10.617 302.464,13.208 302.464,26.34 J1.9@301.117,27.686
CNT10: J1.10 J2.10 J3.10 J4.10 RA6.3 | length 368.2
  Top Layer w0.2: J4.10@3.937,27.686 9.83,27.686 10.999,26.518 10.999,17.094 20.6,7.493 28.896,7.493 28.931,7.458 30.134,7.458 30.404,7.188 62.078,7.188 62.441,6.826 64.027,6.826 64.364,7.163 97.047,7.163 97.587,6.622 100.729,6.622 101.346,7.239 113.538,7.239 115.824,9.525 125.857,9.525 v1(126.619,10.287) ; RA6.3@172.594,22.657 172.594,21.59 173.102,21.082 183.744,21.082 184.074,20.752 184.074,19.914 184.582,19.406 186.665,19.406 187.884,20.625 196.647,20.625 197.46,19.812 279.68,19.812 280.797,18.694 ; J2.10@280.797,14.986 280.797,20.777 286.665,26.645 302.616,26.645 J1.10@303.657,27.686
  Bottom Layer w0.2: v1(126.619,10.287) 129.565,7.341 134.939,7.341 135.726,6.553 144.45,6.553 145.631,5.372 151.826,5.372 153.007,6.553 153.744,6.553 154.811,7.62 163.576,7.62 177.038,21.082 v1(177.75,21.082) ; J2.10@280.797,14.986 280.797,27.026 279.858,27.965 279.858,38.659 280.315,39.116 280.493,39.116 280.797,39.421 J3.10@280.797,40.386
CNT11: J1.11 J2.11 J3.11 J4.11 RA6.2 | length 404.2
  Top Layer w0.2: v1(2.337,12.649) 8.738,6.248 17.78,6.248 18.17,5.858 28.33,5.858 28.804,5.385 60.344,5.385 60.522,5.207 65.812,5.207 65.99,5.385 89.815,5.385 90.145,5.055 95.955,5.055 95.987,5.022 101.709,5.022 101.854,4.877 106.096,4.877 106.426,4.547 117.094,4.547 117.425,4.877 121.133,4.877 123.648,7.391 139.091,7.391 139.777,6.706 143.789,6.706 144.996,5.499 153.459,5.499 155.536,7.576 159.429,7.576 160.09,6.915 165.538,6.915 v1(166.751,8.128) ; v1(176.937,21.844) 176.835,21.742 174.118,21.742 173.864,21.996 RA6.2@173.864,22.657 173.864,23.952 173.457,24.359 173.457,25.248 173.679,25.469 174.752,25.469 174.974,25.248 180.322,25.248 181.389,26.314 190.698,26.314 191.333,25.679 261.57,25.679 271.984,36.093 271.984,41.097 273.05,42.164 288.824,42.164 289.357,41.631 289.357,37.719 290.83,36.246 304.165,36.246 304.597,35.814 304.597,27.28 303.53,26.213 303.251,26.213 302.184,25.146 J1.11@301.117,25.146 ; J3.11@283.337,37.846 284.607,39.116 289.357,39.116
  Bottom Layer w0.2: J4.11@1.397,25.146 2.337,24.206 v1(2.337,12.649) ; v1(166.751,8.128) 166.751,10.21 176.632,20.091 178.246,20.091 178.512,20.357 178.512,21.412 178.08,21.844 v1(176.937,21.844) ; J2.11@283.337,12.446 284.277,13.386 284.277,26.187 283.337,27.127 J3.11@283.337,37.846
CNT12: J1.12 J2.12 J3.12 J4.12 RA6.1 | length 394.2
  Top Layer w0.2: v1(17.145,5.461) 17.148,5.458 28.118,5.458 28.776,4.801 66.218,4.801 66.396,4.978 89.434,4.978 89.79,4.622 101.347,4.622 101.575,4.394 105.461,4.394 105.817,4.039 117.425,4.039 117.856,4.47 121.292,4.47 123.807,6.985 138.862,6.985 139.548,6.299 143.561,6.299 144.761,5.099 153.625,5.099 155.702,7.176 159.194,7.176 159.855,6.515 167.17,6.515 167.945,7.29 v1(167.945,8.738) 168.554,8.738 168.961,8.331 175.87,8.331 177.115,7.087 248.997,7.087 249.479,7.569 286.208,7.569 286.817,8.179 286.817,13.081 286.182,13.716 284.607,13.716 J2.12@283.337,14.986 283.337,19.406 287.732,23.8 303.251,23.8 303.657,24.206 J1.12@303.657,25.146 ; RA6.1@175.134,22.657 v1(177.724,22.657)
  Bottom Layer w0.2: J4.12@3.937,25.146 16.333,25.146 17.145,24.333 v1(17.145,5.461) ; v1(167.945,8.738) 167.945,9.627 178.004,19.685 178.486,19.685 178.918,20.117 178.918,22.174 178.435,22.657 v1(177.724,22.657) ; J2.12@283.337,14.986 283.337,26.543 282.398,27.483 282.398,38.659 282.855,39.116 282.931,39.116 283.337,39.522 J3.12@283.337,40.386
CNT13: J1.13 J2.13 J3.13 J4.13 RA7.4 | length 399.1
  Top Layer w0.2: J4.13@1.397,22.606 2.667,21.336 9.017,21.336 10.11,20.244 10.11,9.398 12.853,6.655 18.492,6.655 18.888,6.258 28.743,6.258 29.21,5.791 60.719,5.791 60.896,5.613 65.431,5.613 65.609,5.791 90.196,5.791 90.526,5.461 96.329,5.461 96.368,5.422 101.893,5.422 102.032,5.283 106.655,5.283 106.985,4.953 116.536,4.953 116.866,5.283 119.685,5.283 122.2,7.798 139.664,7.798 140.35,7.112 143.479,7.112 144.343,7.976 154.534,7.976 155.702,9.144 158.75,9.144 159.311,8.583 160.835,8.583 161.036,8.382 164.719,8.382 166.751,10.414 169.164,10.414 170.307,9.271 181.051,9.271 182.626,7.696 199.34,7.696 200.432,8.788 284.557,8.788 285.877,10.109 J2.13@285.877,12.446 ; RA7.4@179.452,22.657 179.452,23.419 180.468,24.435 181.026,24.435 181.737,25.146 185.598,25.146 185.929,25.477 190.17,25.477 190.882,24.765 195.834,24.765 v1(196.622,23.978)
  Bottom Layer w0.2: v1(196.622,23.978) v1(211.811,8.788) ; J3.13@285.877,37.846 285.877,27.356 286.817,26.416 286.817,13.386 J2.13@285.877,12.446 286.919,11.405 289.052,11.405 289.052,11.43 289.433,11.811 289.433,13.385 289.764,13.716 289.764,21.59 290.78,22.606 J1.13@301.117,22.606
CNT14: J1.14 J2.14 J3.14 J4.14 RA7.3 | length 395.3
  Top Layer w0.2: J4.14@3.937,22.606 3.937,23.266 3.328,23.876 2.998,23.876 2.998,30.937 3.277,31.217 17.552,31.217 26.899,21.869 26.899,13.64 28.093,12.446 97.486,12.446 99.772,14.732 104.521,14.732 105.283,15.494 122.555,15.494 v1(123.317,14.732) ; RA7.3@180.722,22.657 180.722,23.496 181.102,23.876 181.534,23.876 v1(182.017,24.359) 185.534,24.359 186.252,25.077 189.764,25.077 190.482,24.359 192.583,24.359 193.904,23.038 273.152,23.038 274.778,24.663 274.778,40.894 275.209,41.326 284.938,41.326 J3.14@285.877,40.386 ; J2.14@285.877,14.986 285.877,20.244 286.995,21.361 301.346,21.361 302.387,22.403 302.387,22.606 J1.14@303.657,22.606
  Bottom Layer w0.2: v1(123.317,14.732) 123.317,9.398 123.654,9.061 126.194,9.061 128.886,6.369 134.404,6.369 134.62,6.153 144.215,6.153 145.396,4.972 151.992,4.972 153.173,6.153 153.91,6.153 154.97,7.214 167.59,7.214 169.622,9.246 169.622,10.668 178.08,19.126 179.883,19.126 180.721,19.964 180.721,23.063 v1(182.017,24.359) ; J2.14@285.877,14.986 285.877,25.476 284.938,26.416 284.938,38.684 285.877,39.624 J3.14@285.877,40.386
CNT15: J1.15 J2.15 J3.15 J4.15 RA7.2 | length 378.1
  Top Layer w0.2: J4.15@1.397,20.066 2.591,18.872 v1(8.001,18.872) ; v1(14.326,12.548) 14.91,12.548 20.371,7.087 28.496,7.087 28.525,7.058 29.925,7.058 30.303,6.68 61.697,6.68 61.952,6.426 64.541,6.426 64.796,6.68 96.723,6.68 97.181,6.222 103.276,6.222 v1(103.505,6.452) ; v1(103.505,3.632) 117.831,3.632 118.263,4.064 122.251,4.064 124.765,6.579 138.405,6.579 139.091,5.893 143.256,5.893 144.45,4.699 154.051,4.699 156.128,6.776 158.959,6.776 159.62,6.115 167.43,6.115 168.529,7.214 169.114,7.214 169.469,7.569 v1(169.596,7.569) 169.952,7.925 175.032,7.925 176.276,6.68 250.14,6.68 250.292,6.833 287.478,6.833 288.417,7.772 J2.15@288.417,12.446 287.478,13.386 287.478,19.152 288.392,20.066 J1.15@301.117,20.066 ; RA7.2@181.992,22.657 181.992,23.571 v1(184.379,23.571)
  Bottom Layer w0.2: v1(8.001,18.872) v1(14.326,12.548) ; v1(103.505,3.632) v1(103.505,6.452) ; v1(169.596,7.569) 173.584,11.557 173.584,11.938 183.668,22.022 183.668,22.86 v1(184.379,23.571) ; J2.15@288.417,12.446 288.417,13.462 289.357,14.402 289.357,26.416 288.417,27.356 J3.15@288.417,37.846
